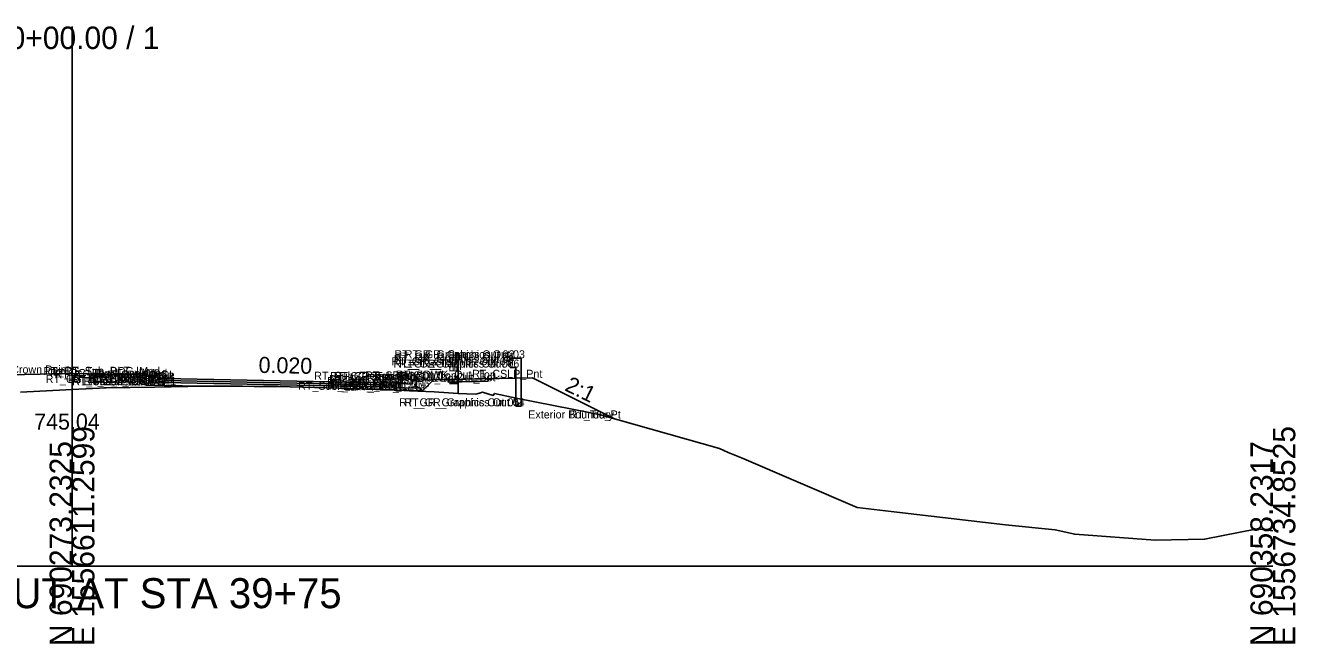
# Model space of a CAD drawing. Extents: x -26 to 6300, y -10 to 9577.
# Drawn here: x 144.2 to 302.8, y 6490.3 to 6567.5 of the extents above; entities that cross this region are included whole.
import ezdxf

# ---------------------------------------------------------------- set-up
doc = ezdxf.new("R2010")
doc.units = 0
for name, color, linetype in [('Default', 7, 'Continuous'), ('Exist CMT Pavement', 7, 'Continuous'), ('Exist Cross Section Cell', 7, 'Continuous'), ('Exist XS Center Line Elevation Label', 7, 'Continuous'), ('Exist XS Ground Line', 7, 'Continuous'), ('Prop CMT Conc Surface', 7, 'Continuous'), ('Prop CMT Concrete Structures', 7, 'Continuous'), ('Prop CMT Guardrail Graphics', 7, 'Continuous'), ('Prop CMT Pvmt Course 1', 7, 'Continuous'), ('Prop CMT Pvmt Course 1 CG', 7, 'Continuous'), ('Prop CMT Pvmt Course 2', 7, 'Continuous'), ('Prop CMT Pvmt Course 3', 7, 'Continuous'), ('Prop CMT Pvmt Surface', 7, 'Continuous'), ('Prop CMT Slope Grass', 7, 'Continuous'), ('Prop CMT Subgrade Earthwork', 7, 'Continuous'), ('Prop XS Label Text', 7, 'Continuous'), ('Prop XS SE Text', 7, 'Continuous'), ('Prop XS Side Slope Text', 7, 'Continuous'), ('Prop XSC Text', 7, 'Continuous')]:
    doc.layers.add(name, color=color, linetype=linetype)

msp = doc.modelspace()

# ---------------------------------------------------------------- linework, layer by layer
at = {"layer": 'Exist CMT Pavement'}
msp.add_lwpolyline([(166.1, 6522.45), (168.19, 6522.46), (169.86, 6522.45), (171.3, 6522.45), (172.75, 6522.44), (174.06, 6522.42), (175.76, 6522.41), (178.77, 6522.32), (181.79, 6522.24), (184.82, 6522.17), (187.85, 6522.1), (188.5, 6522.07)], dxfattribs=at)
at = {"layer": 'Exist Cross Section Cell'}
for p, q in [((150, 6500), (150, 6567.38)), ((0, 6500), (150, 6500)), ((150, 6500), (300, 6500))]:
    msp.add_line(p, q, dxfattribs=at)
at = {"layer": 'Exist XS Ground Line'}
msp.add_lwpolyline([(143.57, 6521.71), (149.23, 6522.02), (150, 6522.06), (154.26, 6522.26), (160.3, 6522.36), (166.53, 6522.46), (169.86, 6522.45), (172.75, 6522.44), (174.06, 6522.42), (175.76, 6522.41), (181.79, 6522.24), (187.85, 6522.1), (190.04, 6521.99), (192.16, 6521.9), (195.23, 6521.74), (198.23, 6521.57), (199.3, 6521.5), (200.46, 6521.45), (200.9, 6521.6), (201.26, 6521.72), (202.62, 6521.31), (202.79, 6521.55), (205.5, 6520.96), (214.8, 6519.15), (215.56, 6518.95), (216.01, 6518.9), (230.88, 6514.66), (231.96, 6514.19), (233.64, 6513.5), (248.06, 6507.29), (253.04, 6506.73), (266.59, 6505.16), (272.79, 6504.52), (275.25, 6503.97), (285.31, 6503.24), (291.48, 6503.34), (298.02, 6504.64), (300, 6504.39)], dxfattribs=at)
at = {"layer": 'Prop CMT Conc Surface'}
for points in [[(161.5, 6523.42), (160.75, 6523.44), (160.75, 6523.6), (159.99, 6523.85)], [(190.5, 6522.84), (192.5, 6522.72)], [(192.5, 6522.72), (192.5, 6523.22), (193, 6523.22)], [(197, 6523.31), (202, 6523.41)]]:
    msp.add_lwpolyline(points, dxfattribs=at)
at = {"layer": 'Prop CMT Concrete Structures'}
for points in [[(161.5, 6523.42), (160.75, 6523.44), (160.75, 6523.6), (159.99, 6523.85)], [(159.99, 6523.85), (159.99, 6522.87)], [(159.99, 6522.87), (161.5, 6522.84)], [(161.5, 6522.84), (161.5, 6523.42)], [(190.5, 6522.84), (192.5, 6522.72), (192.5, 6523.22), (193, 6523.22)], [(193, 6523.22), (193, 6522.21), (190.5, 6522.26)], [(190.5, 6522.26), (190.5, 6522.84)], [(202, 6523.41), (197, 6523.31)], [(197, 6523.31), (197, 6522.98)], [(197, 6522.98), (202, 6523.08)], [(202, 6523.08), (202, 6523.41)]]:
    msp.add_lwpolyline(points, dxfattribs=at)
at = {"layer": 'Prop CMT Guardrail Graphics'}
for points in [[(206.1, 6525.95), (204.77, 6525.95), (204.5, 6525.66)], [(206.1, 6519.95), (206.1, 6525.95)], [(204.5, 6525.66), (204.77, 6525.37)], [(204.77, 6525.37), (204.5, 6525.08)], [(204.5, 6525.08), (204.77, 6524.79), (205.44, 6524.79)], [(205.44, 6524.79), (205.44, 6519.95)], [(205.44, 6519.95), (206.1, 6519.95)]]:
    msp.add_lwpolyline(points, dxfattribs=at)
at = {"layer": 'Prop CMT Pvmt Course 1'}
for points in [[(161.5, 6523.42), (190.5, 6522.84)], [(161.5, 6523.17), (161.5, 6523.42)], [(190.5, 6522.59), (161.5, 6523.17)], [(161.5, 6523.17), (161.5, 6523.17), (161.5, 6523.17)], [(188.5, 6522.88), (188.5, 6522.63)], [(190.5, 6522.84), (190.5, 6522.59)]]:
    msp.add_lwpolyline(points, dxfattribs=at)
at = {"layer": 'Prop CMT Pvmt Course 1 CG'}
for points in [[(161.5, 6522.84), (159.49, 6522.88), (159.2, 6522.59)], [(161.5, 6522.59), (161.5, 6522.84)], [(159.24, 6522.59), (161.5, 6522.55)], [(193.8, 6521.9), (188.5, 6522.01)], [(190.5, 6522.26), (193.5, 6522.2), (193.8, 6521.9)], [(190.5, 6522.01), (190.5, 6522.26)]]:
    msp.add_lwpolyline(points, dxfattribs=at)
at = {"layer": 'Prop CMT Pvmt Course 2'}
for points in [[(161.5, 6522.92), (161.5, 6523.17)], [(161.5, 6523.17), (190.5, 6522.59)], [(190.5, 6522.34), (161.5, 6522.92)], [(188.5, 6522.63), (188.5, 6522.38)], [(190.5, 6522.59), (190.5, 6522.34)]]:
    msp.add_lwpolyline(points, dxfattribs=at)
at = {"layer": 'Prop CMT Pvmt Course 3'}
for points in [[(161.5, 6522.92), (190.5, 6522.34)], [(161.5, 6522.55), (161.5, 6522.92)], [(166.1, 6522.45), (161.5, 6522.55)], [(188.5, 6522.38), (188.5, 6522.01)], [(190.5, 6522.34), (190.5, 6521.97)]]:
    msp.add_lwpolyline(points, dxfattribs=at)
at = {"layer": 'Prop CMT Pvmt Surface'}
msp.add_lwpolyline([(161.5, 6523.42), (190.5, 6522.84)], dxfattribs=at)
at = {"layer": 'Prop CMT Slope Grass'}
for points in [[(140.01, 6523.85), (150, 6524.05)], [(159.99, 6523.85), (150, 6524.05)], [(193, 6523.22), (207.5, 6523.51)], [(207.5, 6523.51), (217.67, 6518.43)]]:
    msp.add_lwpolyline(points, dxfattribs=at)
at = {"layer": 'Prop CMT Subgrade Earthwork'}
for p, q in [((193.8, 6521.9), (195.16, 6523.26)), ((188.5, 6522.01), (188.5, 6522.07))]:
    msp.add_line(p, q, dxfattribs=at)
for points in [[(157.9, 6523.89), (159.2, 6522.59)], [(159.2, 6522.59), (161.5, 6522.55)], [(161.5, 6522.55), (161.5, 6522.55)], [(161.5, 6522.55), (166.1, 6522.45)], [(188.5, 6522.01), (193.8, 6521.9)]]:
    msp.add_lwpolyline(points, dxfattribs=at)
at = {"layer": 'Prop XS Label Text'}
msp.add_line((198.23, 6526.57), (198.23, 6521.57), dxfattribs=at)

# ---------------------------------------------------------------- texts
at = {"layer": 'Default'}
for s, p in [('RT_GR_Graphics Out 08', (189.92, 6525.08)), ('RT_GR_Graphics Out 07', (190.17, 6524.79)), ('RT_GR_Graphics Out 09', (190.2, 6525.37)), ('RT_GR_Graphics Out 02', (190.26, 6525.95)), ('RT_GR_Graphics Out 01', (190.28, 6525.66)), ('RT_GR_Graphics Out 06', (190.86, 6524.79)), ('RT_GR_Graphics Out 03', (191.56, 6525.95)), ('MD_Crown Point', (139.58, 6524.05)), ('RT_CG_Top_BOC_Med', (146.43, 6523.85)), ('RT_CG_Top_Face_Med', (147.25, 6523.6)), ('RT_CG_Top_Gut_Med', (147.8, 6523.44)), ('RT_Sub_DLT_In', (149.07, 6523.89)), ('RT_PV1_PGL', (154.38, 6523.42)), ('RT_Sub_Trench_Out_DLT', (180.26, 6523.26)), ('RT_CG_Top_Face', (182.22, 6523.22)), ('RT_CG_Top_BOC', (182.69, 6523.22)), ('RT_SDWK_In_Top', (186.62, 6523.31)), ('RT_SDWK_Out_Top', (190.46, 6523.41)), ('RT_CSLP_Pnt', (199.98, 6523.51)), ('RT_CG_Bot_BOC_Med', (146.71, 6522.87)), ('RT_CG1_Shelf_In', (149.57, 6522.88)), ('RT_CG_Bot_IE_Med', (149.98, 6522.84)), ('RT_Sub_IEOT_CG_1', (150.01, 6522.59)), ('RT_Sub_IEOP', (151.42, 6522.63)), ('RT_PV2_OEEOP', (152.17, 6523.17)), ('RT_PV3_OEEOP', (152.17, 6522.92)), ('RT_Sub_OEEOP', (152.21, 6522.55)), ('RT_PV2_IEEOP', (152.93, 6523.17)), ('RT_Sub_IEEOP', (152.97, 6522.55)), ('RT_PV2_PGL', (154.15, 6523.17)), ('RT_Sub_PGL', (154.19, 6522.55)), ('RT_Sub_OEOT_CG_1', (178.25, 6522.01)), ('RT_PV2_OEOT', (181.87, 6522.59)), ('RT_PV3_OEOT', (181.87, 6522.34)), ('RT_Sub_OEOT', (181.92, 6521.97)), ('RT_PV1_OEOT', (182.11, 6522.84)), ('RT_CG_Bot_IE', (182.22, 6522.26)), ('RT_CG1_Shelf_Out', (182.36, 6522.2)), ('RT_CG_Top_Gut', (182.75, 6522.72)), ('RT_CG_Bot_BOC', (182.97, 6522.21)), ('RT_Sub_OEOP', (185.17, 6521.94)), ('RT_SDWK_In_Bot', (186.87, 6522.98)), ('RT_SDWK_Out_Bot', (190.71, 6523.08)), ('RT_GR_Graphics Out 05', (190.88, 6519.95)), ('RT_GR_Graphics Out 04', (191.52, 6519.95)), ('Exterior Boundary', (206.99, 6518.43)), ('RT_Tie_Pt', (212.15, 6518.43))]:
    msp.add_text(s, height=1, dxfattribs=at).set_placement(p)
at = {"layer": 'Exist Cross Section Cell'}
msp.add_text('40+00.00 / 1', height=2.8, dxfattribs=at).set_placement((140, 6564.58))
for s, p in [('E 1556611.2599', (152.8, 6490)), ('E 1556734.8525', (302.8, 6490)), ('N 690273.2325', (150, 6490)), ('N 690358.2317', (300, 6490))]:
    msp.add_text(s, height=2.8, rotation=90, dxfattribs=at).set_placement(p)
at = {"layer": 'Exist XS Center Line Elevation Label'}
msp.add_text('745.04', height=2, dxfattribs=at).set_placement((145.28, 6517.04))
at = {"layer": 'Prop XS Label Text'}
msp.add_text('E. EOP', height=1, rotation=90, dxfattribs=at).set_placement((198.13, 6522.59))
at = {"layer": 'Prop XS SE Text'}
msp.add_text('0.020', height=2, rotation=358.8542, dxfattribs=at).set_placement((173.29, 6524.13))
at = {"layer": 'Prop XS Side Slope Text'}
msp.add_text('2:1', height=2, rotation=333.9281, dxfattribs=at).set_placement((211.43, 6521.98))
at = {"layer": 'Prop XSC Text'}
msp.add_text('BEGIN UNDERCUT AT STA 39+75', height=3.75, dxfattribs=at).set_placement((104.12, 6494.73))

doc.saveas('drawing.dxf')
